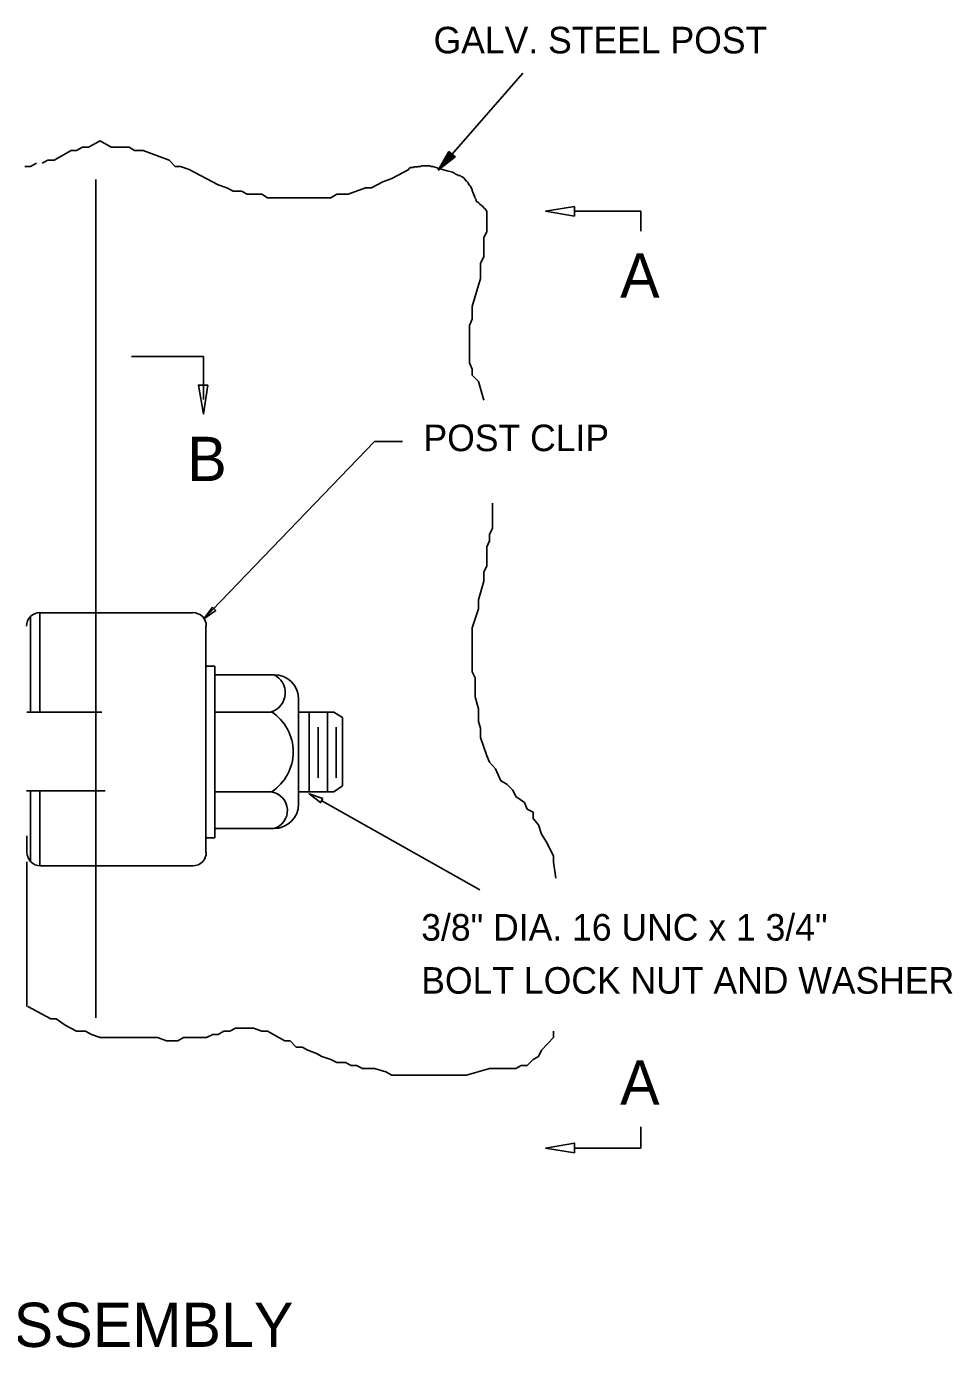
# Model space of a CAD drawing. Extents: x 150.3 to 157.3, y 91.3 to 101.4.
# Drawn here: x 151.88 to 153.972, y 98.396 to 101.381 of the extents above; entities that cross this region are included whole.
import ezdxf

# ---------------------------------------------------------------- set-up
doc = ezdxf.new("R2010")
doc.units = 0
for name, color, linetype in [('DETL-DIMS', 7, 'Continuous'), ('DETL-LINE', 7, 'Continuous'), ('DETL-NOTE', 7, 'Continuous'), ('DETL-TITL', 7, 'Continuous')]:
    doc.layers.add(name, color=color, linetype=linetype)

msp = doc.modelspace()

# ---------------------------------------------------------------- linework, layer by layer
at = {"layer": 'DETL-DIMS'}
for p, q in [((152.81, 101.0563), (153.0014, 101.2755)), ((152.0367, 101.0347), (152.0367, 99.1413)), ((153.1175, 100.9638), (153.2675, 100.9638)), ((153.2675, 100.9638), (153.2675, 100.918)), ((152.28, 100.6355), (152.1175, 100.6355)), ((152.28, 100.538), (152.28, 100.6355)), ((152.2808, 100.0422), (152.6658, 100.443)), ((152.6658, 100.443), (152.7292, 100.443)), ((152.5475, 99.6313), (152.9042, 99.4305)), ((153.2675, 98.8463), (153.2675, 98.8947)), ((153.1175, 98.8463), (153.2675, 98.8463))]:
    msp.add_line(p, q, dxfattribs=at)
for points in [[(152.8342, 101.098), (152.81, 101.0563), (152.8483, 101.0863), (152.8342, 101.098)], [(152.8342, 101.0963), (152.8142, 101.0613), (152.8467, 101.0863), (152.8342, 101.0963)], [(152.835, 101.0947), (152.8183, 101.0655), (152.8442, 101.0863), (152.835, 101.0947)], [(152.835, 101.093), (152.8217, 101.0705), (152.8425, 101.0863), (152.835, 101.093)], [(152.8358, 101.0913), (152.8258, 101.0755), (152.8408, 101.0863), (152.8358, 101.0913)], [(152.8358, 101.0897), (152.83, 101.0797), (152.8383, 101.0863), (152.8358, 101.0897)], [(152.8358, 101.0872), (152.8342, 101.0847), (152.8375, 101.0863), (152.8358, 101.0872)]]:
    msp.add_lwpolyline(points, dxfattribs=at)
for points in [[(153.1175, 100.9522), (153.1175, 100.9738), (153.0525, 100.9638)], [(152.29, 100.5705), (152.2683, 100.5705), (152.28, 100.5055)], [(152.3, 100.0688), (152.3075, 100.0613), (152.2808, 100.0422)], [(152.5492, 99.6363), (152.5442, 99.6272), (152.5183, 99.6472)], [(153.1175, 98.8363), (153.1175, 98.858), (153.0525, 98.8463)]]:
    msp.add_lwpolyline(points, close=True, dxfattribs=at)
at = {"layer": 'DETL-LINE'}
for p, q in [((151.9808, 101.1005), (151.9425, 101.0788)), ((151.9933, 101.1005), (151.9808, 101.1005)), ((152.0067, 101.108), (151.9933, 101.1005)), ((152.02, 101.108), (152.0067, 101.108)), ((152.0467, 101.1222), (152.02, 101.108)), ((152.0717, 101.108), (152.0467, 101.1222)), ((152.1117, 101.108), (152.0717, 101.108)), ((152.1242, 101.1005), (152.1117, 101.108)), ((152.1433, 101.1005), (152.1242, 101.1005)), ((152.2025, 101.0788), (152.1433, 101.1005)), ((151.9025, 101.0722), (151.8892, 101.0647)), ((151.9283, 101.0788), (151.9158, 101.0722)), ((151.9425, 101.0788), (151.9283, 101.0788)), ((152.2158, 101.0647), (152.2025, 101.0788)), ((151.8892, 101.0647), (151.8767, 101.0647)), ((152.2283, 101.0647), (152.2158, 101.0647)), ((152.2475, 101.058), (152.2283, 101.0647)), ((152.3133, 101.023), (152.2475, 101.058)), ((152.7433, 101.058), (152.705, 101.0372)), ((152.745, 101.0597), (152.7433, 101.0597)), ((152.7433, 101.0597), (152.7433, 101.058)), ((152.7467, 101.0622), (152.745, 101.0597)), ((152.7533, 101.0622), (152.7467, 101.0622)), ((152.7558, 101.0638), (152.7533, 101.0622)), ((152.7633, 101.0638), (152.7558, 101.0638)), ((152.7658, 101.0647), (152.7633, 101.0638)), ((152.7708, 101.0647), (152.7658, 101.0647)), ((152.7725, 101.0663), (152.7708, 101.0647)), ((152.7917, 101.0663), (152.7725, 101.0663)), ((152.7933, 101.0647), (152.7917, 101.0663)), ((152.7975, 101.0647), (152.7933, 101.0647)), ((152.8, 101.0638), (152.7975, 101.0647)), ((152.805, 101.0622), (152.8, 101.0638)), ((152.8117, 101.0597), (152.805, 101.0622)), ((152.83, 101.0547), (152.8117, 101.0597)), ((152.8333, 101.0538), (152.83, 101.0547)), ((152.8425, 101.0513), (152.8333, 101.0538)), ((152.8467, 101.0497), (152.8425, 101.0513)), ((152.8492, 101.0472), (152.8467, 101.0497)), ((152.8533, 101.0455), (152.8492, 101.0472)), ((152.855, 101.0438), (152.8533, 101.0455)), ((152.8592, 101.0438), (152.855, 101.0438)), ((152.8617, 101.0422), (152.8592, 101.0438)), ((152.8642, 101.0413), (152.8617, 101.0422)), ((152.8675, 101.0388), (152.8642, 101.0413)), ((152.3325, 101.0163), (152.3133, 101.023)), ((152.3467, 101.0088), (152.3325, 101.0163)), ((152.6458, 101.0163), (152.6067, 101.0022)), ((152.6592, 101.0163), (152.6458, 101.0163)), ((152.685, 101.0297), (152.6592, 101.0163)), ((152.705, 101.0372), (152.685, 101.0297)), ((152.8683, 101.0372), (152.8675, 101.0388)), ((152.8742, 101.0313), (152.8683, 101.0372)), ((152.8758, 101.0288), (152.8742, 101.0313)), ((152.8783, 101.0263), (152.8758, 101.0288)), ((152.88, 101.0222), (152.8783, 101.0263)), ((152.8825, 101.0205), (152.88, 101.0222)), ((152.8833, 101.0188), (152.8825, 101.0205)), ((152.885, 101.0147), (152.8833, 101.0188)), ((152.8867, 101.0122), (152.885, 101.0147)), ((152.8867, 101.0097), (152.8867, 101.0122)), ((152.3658, 101.0088), (152.3467, 101.0088)), ((152.3783, 101.0022), (152.3658, 101.0088)), ((152.4117, 101.0022), (152.3783, 101.0022)), ((152.4242, 100.9938), (152.4117, 101.0022)), ((152.5675, 100.9938), (152.4242, 100.9938)), ((152.5808, 101.0022), (152.5675, 100.9938)), ((152.6067, 101.0022), (152.5808, 101.0022)), ((152.8883, 101.0063), (152.8867, 101.0097)), ((152.8925, 100.9955), (152.8883, 101.0063)), ((152.8933, 100.9922), (152.8925, 100.9955)), ((152.8958, 100.9897), (152.8933, 100.9922)), ((152.8958, 100.9872), (152.8958, 100.9897)), ((152.8975, 100.9847), (152.8958, 100.9872)), ((152.9008, 100.983), (152.8975, 100.9847)), ((152.9017, 100.9813), (152.9008, 100.983)), ((152.9042, 100.9797), (152.9017, 100.9813)), ((152.9075, 100.9763), (152.9042, 100.9797)), ((152.91, 100.9747), (152.9075, 100.9763)), ((152.9142, 100.9697), (152.91, 100.9747)), ((152.9175, 100.9672), (152.9142, 100.9697)), ((152.92, 100.9622), (152.9175, 100.9672)), ((152.92, 100.9597), (152.92, 100.9622)), ((152.92, 100.9172), (152.92, 100.9597)), ((152.9133, 100.903), (152.92, 100.9172)), ((152.9133, 100.8888), (152.9133, 100.903)), ((152.9133, 100.8605), (152.9133, 100.8888)), ((152.9058, 100.8463), (152.9133, 100.8605)), ((152.9058, 100.8113), (152.9058, 100.8463)), ((152.8867, 100.748), (152.9058, 100.8113)), ((152.8867, 100.7197), (152.8867, 100.748)), ((152.8808, 100.7055), (152.8867, 100.7197)), ((152.8808, 100.6205), (152.8808, 100.7055)), ((152.8867, 100.6063), (152.8808, 100.6205)), ((152.8867, 100.593), (152.8867, 100.6063)), ((152.9008, 100.5788), (152.8867, 100.593)), ((152.9133, 100.5363), (152.9008, 100.5788)), ((152.9325, 100.2472), (152.9325, 100.3038)), ((152.9258, 100.233), (152.9325, 100.2472)), ((152.92, 100.2055), (152.9258, 100.2188)), ((152.92, 100.1622), (152.92, 100.2055)), ((152.9258, 100.2188), (152.9258, 100.233)), ((152.9133, 100.148), (152.92, 100.1622)), ((152.9133, 100.1272), (152.9133, 100.148)), ((152.9008, 100.0855), (152.9133, 100.1272)), ((152.9008, 100.0647), (152.9008, 100.0855)), ((152.255, 100.0563), (151.91, 100.0563)), ((151.91, 100.0563), (151.9108, 100.0563)), ((151.91, 100.0563), (151.91, 99.8313)), ((152.8867, 100.0222), (152.9008, 100.0647)), ((151.889, 100.0475), (151.889, 99.8313)), ((152.285, 100.0105), (152.285, 100.0263)), ((152.285, 100.0105), (152.285, 99.5147)), ((152.8867, 99.923), (152.8867, 100.0222)), ((152.3058, 99.9355), (152.285, 99.9355)), ((152.3058, 99.883), (152.3058, 99.9355)), ((152.4383, 99.9163), (152.3058, 99.9163)), ((152.8933, 99.9088), (152.8867, 99.923)), ((152.8933, 99.8663), (152.8933, 99.9088)), ((152.3058, 99.883), (152.3058, 99.6022)), ((152.4942, 99.6213), (152.4942, 99.8622)), ((152.9008, 99.8388), (152.8933, 99.8663)), ((151.8808, 99.8313), (152.0502, 99.8313)), ((152.4325, 99.8313), (152.3058, 99.8313)), ((152.5742, 99.8313), (152.4942, 99.8313)), ((152.5183, 99.6513), (152.5183, 99.8313)), ((152.56, 99.6513), (152.56, 99.8313)), ((152.5942, 99.8197), (152.5742, 99.8313)), ((152.5942, 99.8197), (152.5942, 99.6655)), ((152.9008, 99.8105), (152.9008, 99.8388)), ((152.5392, 99.683), (152.5392, 99.798)), ((152.5792, 99.683), (152.5792, 99.798)), ((152.9058, 99.7955), (152.9008, 99.8105)), ((152.9058, 99.7747), (152.9058, 99.7955)), ((152.92, 99.733), (152.9058, 99.7747)), ((152.9258, 99.7188), (152.92, 99.733)), ((152.9392, 99.7038), (152.9258, 99.7188)), ((152.9517, 99.6763), (152.9392, 99.7038)), ((152.965, 99.6688), (152.9517, 99.6763)), ((152.9783, 99.6555), (152.965, 99.6688)), ((151.88, 99.6538), (152.0575, 99.6538)), ((151.889, 99.6522), (151.889, 99.4935)), ((151.91, 99.6522), (151.91, 99.4846)), ((152.4325, 99.6513), (152.3058, 99.6513)), ((152.4942, 99.6513), (152.5742, 99.6513)), ((152.5742, 99.6513), (152.5942, 99.6655)), ((152.985, 99.6413), (152.9783, 99.6555)), ((153.005, 99.6272), (152.985, 99.6413)), ((153.0108, 99.6122), (153.005, 99.6272)), ((153.0242, 99.6055), (153.0108, 99.6122)), ((152.3058, 99.6022), (152.3058, 99.548)), ((153.0242, 99.5913), (153.0242, 99.6055)), ((153.0367, 99.5772), (153.0242, 99.5913)), ((151.8808, 99.5522), (151.8808, 99.5147)), ((152.3058, 99.548), (152.285, 99.548)), ((152.3058, 99.5688), (152.4383, 99.5688)), ((153.0433, 99.5563), (153.0367, 99.5772)), ((153.0558, 99.5355), (153.0433, 99.5563)), ((153.07, 99.5063), (153.0558, 99.5355)), ((151.8808, 99.4938), (151.8808, 99.1663)), ((151.9108, 99.4847), (152.255, 99.4847)), ((151.8833, 99.1663), (151.935, 99.1388)), ((151.935, 99.1388), (151.9475, 99.1388)), ((151.9475, 99.1388), (151.9675, 99.1247)), ((151.9675, 99.1247), (151.9933, 99.1105)), ((151.9933, 99.1105), (152.0133, 99.1105)), ((152.0133, 99.1105), (152.0267, 99.103)), ((152.0267, 99.103), (152.0467, 99.0963)), ((152.2867, 99.0963), (152.3008, 99.103)), ((152.3008, 99.103), (152.3133, 99.103)), ((152.3133, 99.103), (152.3258, 99.1105)), ((152.3258, 99.1105), (152.3392, 99.1105)), ((152.3392, 99.1105), (152.3525, 99.118)), ((152.3525, 99.118), (152.3925, 99.118)), ((152.3925, 99.118), (152.4117, 99.1105)), ((152.4117, 99.1105), (152.4242, 99.1105)), ((152.4242, 99.1105), (152.4633, 99.0888)), ((153.07, 99.0963), (153.07, 99.1105)), ((152.0467, 99.0963), (152.1758, 99.0963)), ((152.1758, 99.0963), (152.1967, 99.0888)), ((152.1967, 99.0888), (152.2217, 99.0888)), ((152.2217, 99.0888), (152.235, 99.0963)), ((152.235, 99.0963), (152.2867, 99.0963)), ((152.4633, 99.0888), (152.4758, 99.0888)), ((152.4758, 99.0888), (152.4892, 99.0747)), ((152.4892, 99.0747), (152.5025, 99.0747)), ((152.5025, 99.0747), (152.5158, 99.068)), ((153.0433, 99.068), (153.07, 99.0963)), ((152.5158, 99.068), (152.535, 99.0605)), ((152.535, 99.0605), (152.5475, 99.0538)), ((152.5475, 99.0538), (152.5675, 99.0472)), ((152.5675, 99.0472), (152.5808, 99.0397)), ((153.0108, 99.033), (153.0242, 99.0472)), ((153.0242, 99.0472), (153.0367, 99.0538)), ((153.0367, 99.0538), (153.0433, 99.068)), ((152.5808, 99.0397), (152.6008, 99.0397)), ((152.6008, 99.0397), (152.6133, 99.033)), ((152.6133, 99.033), (152.6258, 99.033)), ((152.6258, 99.033), (152.6392, 99.0263)), ((152.6392, 99.0263), (152.6658, 99.0263)), ((152.6658, 99.0263), (152.6917, 99.0188)), ((152.6917, 99.0188), (152.705, 99.0113)), ((152.705, 99.0113), (152.8742, 99.0113)), ((152.8742, 99.0113), (152.9258, 99.0263)), ((152.9258, 99.0263), (152.985, 99.0263)), ((152.985, 99.0263), (152.9975, 99.033)), ((152.9975, 99.033), (153.0108, 99.033))]:
    msp.add_line(p, q, dxfattribs=at)
msp.add_lwpolyline([(153.0758, 99.4563), (153.07, 99.493), (153.07, 99.5063)], dxfattribs=at)
for centre, radius, start, end in [((151.9104, 100.026), 0.0304, 90, 180), ((152.2559, 100.026), 0.0304, 0, 90), ((152.4194, 99.8753), 0.0452, 288.331, 64.9752), ((152.4386, 99.8601), 0.0562, 0, 90), ((152.3743, 99.7419), 0.1082, 303.3007, 56.6993), ((152.4271, 99.6095), 0.0424, 285.6771, 81.1109), ((152.4386, 99.6248), 0.0562, 270, 0), ((151.9116, 99.515), 0.0304, 180, 270), ((152.2559, 99.515), 0.0304, 270, 0)]:
    msp.add_arc(centre, radius, start, end, dxfattribs=at)

# ---------------------------------------------------------------- texts
at = {"layer": 'DETL-NOTE'}
for s, height, p in [('GALV. STEEL POST', 0.06, (152.7995, 101.32)), ('A', 0.1, (153.2208, 100.768)), ('POST CLIP', 0.06, (152.7767, 100.4213)), ('B', 0.1, (152.2433, 100.3538)), ('3/8" DIA. 16 UNC x 1 3/4" ', 0.06, (152.7717, 99.3155)), ('BOLT LOCK NUT AND WASHER', 0.06, (152.7717, 99.1955)), ('A', 0.1, (153.2208, 98.9447))]:
    msp.add_text(s, height=height, dxfattribs=at).set_placement(p)
at = {"layer": 'DETL-TITL'}
msp.add_text('SIGN PANEL ASSEMBLY', height=0.1, dxfattribs=at).set_placement((150.9223, 98.3974))

doc.saveas('drawing.dxf')
